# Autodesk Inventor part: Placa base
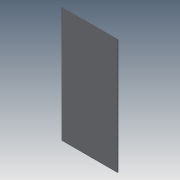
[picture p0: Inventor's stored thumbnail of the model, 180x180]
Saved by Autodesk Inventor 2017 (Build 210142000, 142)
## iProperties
Created: 2019-03
Part Number: Placa base
Material: Generic
Document SubType Name: Modeling
Designer: user
Density: 1 g/cm^3
Appearance: Default
Author: user
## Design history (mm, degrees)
sketch "Sketch1"
  geometry: L1 (0, 0)-(-300, 0); L2 (-300, 0)-(-300, 620); L3 (-300, 620)-(0, 620); L4 (0, 620)-(0, 0)
  constraints: 8 end point, 2 parallel, 1 horizontal, 1 perpendicular
  dimensions: "d0" = 300 distance of L2.end L3.end; "d1" = 620 distance of L1.end L2.end
extrude "Extrusion1" new body sketch "Sketch1" distance "d2" = 3; taper "d3" = 0 deg
body "Solid1"
